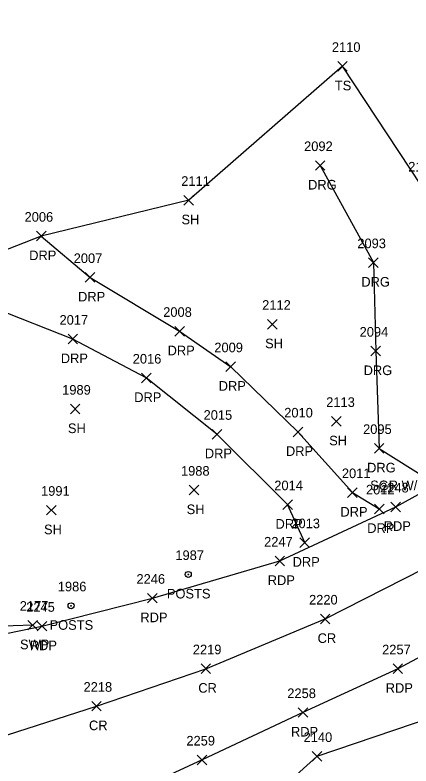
# Model space of a CAD drawing. Extents: x 1616726 to 1619875, y 273782 to 276557.
# Drawn here: x 1616975.5 to 1617057.8, y 276373.3 to 276529.6 of the extents above; entities that cross this region are included whole.
import ezdxf

# ---------------------------------------------------------------- set-up
doc = ezdxf.new("R2010")
doc.units = 0
for name, color, linetype in [('L_A', 7, 'Continuous'), ('L_I', 7, 'Continuous'), ('L_TIC', 7, 'Continuous'), ('LELB', 7, 'Continuous'), ('LPST', 7, 'Continuous'), ('LSOGP', 7, 'Continuous'), ('P_A', 7, 'Continuous'), ('P_I', 7, 'Continuous'), ('P_TIC', 7, 'Continuous'), ('PET', 7, 'Continuous'), ('PRC', 7, 'Continuous'), ('R_A', 7, 'Continuous'), ('R_C', 7, 'Continuous'), ('R_I', 7, 'Continuous'), ('R_TIC', 7, 'Continuous'), ('RDG', 7, 'Continuous'), ('RDP', 7, 'Continuous'), ('RSW', 7, 'Continuous')]:
    doc.layers.add(name, color=color, linetype=linetype)

msp = doc.modelspace()

# ---------------------------------------------------------------- linework, layer by layer
at = {"layer": 'L_TIC'}
for points in [[(1617042.61, 276517.88), (1617044.61, 276519.88)], [(1617044.61, 276517.88), (1617042.61, 276519.88)], [(1617010.63, 276490), (1617012.63, 276492)], [(1617012.63, 276490), (1617010.63, 276492)], [(1617028.02, 276464.21), (1617030.02, 276466.21)], [(1617030.02, 276464.21), (1617028.02, 276466.21)], [(1616987.01, 276446.55), (1616989.01, 276448.55)], [(1616989.01, 276446.55), (1616987.01, 276448.55)], [(1617041.35, 276444), (1617043.35, 276446)], [(1617043.35, 276444), (1617041.35, 276446)], [(1617011.71, 276429.69), (1617013.71, 276431.69)], [(1617013.71, 276429.69), (1617011.71, 276431.69)], [(1616982.05, 276425.51), (1616984.05, 276427.51)], [(1616984.05, 276425.51), (1616982.05, 276427.51)]]:
    msp.add_lwpolyline(points, dxfattribs=at)
at = {"layer": 'LELB'}
msp.add_lwpolyline([(1617083.01, 276455.2), (1617074.16, 276469.8), (1617060.06, 276493.98), (1617043.61, 276518.88)], dxfattribs=at)
at = {"layer": 'LPST'}
for centre, radius in [((1617011.54, 276413.14), 0.625), ((1617011.54, 276413.14), 0.0833), ((1616987.15, 276406.62), 0.625), ((1616987.15, 276406.62), 0.0833)]:
    msp.add_circle(centre, radius, dxfattribs=at)
at = {"layer": 'LSOGP'}
msp.add_lwpolyline([(1617110.11, 276364.12), (1617113.03, 276383.54), (1617109.95, 276385.21), (1617111.11, 276389.12), (1617115.01, 276408.98), (1617109.21, 276417.76), (1617106.51, 276423.63), (1617105.2, 276425.94), (1617105.81, 276428.23), (1617105.93, 276428.7), (1617104.14, 276431), (1617098, 276438.89), (1617095.99, 276441.39), (1617089.73, 276449.19), (1617088.77, 276449.45), (1617085.55, 276449.8), (1617083.01, 276455.2), (1617074.16, 276469.8), (1617060.06, 276493.98), (1617043.61, 276518.88), (1617011.63, 276491), (1616980.96, 276483.54), (1616950.12, 276471.44)], dxfattribs=at)
at = {"layer": 'P_TIC'}
for points in [[(1617053.69, 276426.2), (1617055.69, 276428.2)], [(1617055.69, 276426.2), (1617053.69, 276428.2)], [(1617029.57, 276414.94), (1617031.57, 276416.94)], [(1617031.57, 276414.94), (1617029.57, 276416.94)], [(1617003.08, 276407.2), (1617005.08, 276409.2)], [(1617005.08, 276407.2), (1617003.08, 276409.2)], [(1617039, 276402.88), (1617041, 276404.88)], [(1617041, 276402.88), (1617039, 276404.88)], [(1616980.09, 276401.37), (1616982.09, 276403.37)], [(1616982.09, 276401.37), (1616980.09, 276403.37)], [(1617014.18, 276392.53), (1617016.18, 276394.53)], [(1617016.18, 276392.53), (1617014.18, 276394.53)], [(1617054.11, 276392.51), (1617056.11, 276394.51)], [(1617056.11, 276392.51), (1617054.11, 276394.51)], [(1616991.45, 276384.73), (1616993.45, 276386.73)], [(1616993.45, 276384.73), (1616991.45, 276386.73)], [(1617034.39, 276383.41), (1617036.39, 276385.41)], [(1617036.39, 276383.41), (1617034.39, 276385.41)], [(1617013.4, 276373.54), (1617015.4, 276375.54)], [(1617015.4, 276373.54), (1617013.4, 276375.54)]]:
    msp.add_lwpolyline(points, dxfattribs=at)
at = {"layer": 'PET'}
msp.add_lwpolyline([(1616962.48, 276398.53), (1616981.09, 276402.37), (1617004.08, 276408.2), (1617030.57, 276415.94), (1617054.69, 276427.2), (1617070.17, 276435.74), (1617083.87, 276444.95), (1617089.73, 276449.19), (1617098, 276438.89), (1617105.93, 276428.7), (1617091.93, 276417.88), (1617075.61, 276407.18), (1617070.48, 276401.74), (1617055.11, 276393.51), (1617035.39, 276384.41), (1617014.4, 276374.54), (1616987.83, 276362.23)], dxfattribs=at)
at = {"layer": 'PRC'}
msp.add_lwpolyline([(1616941.59, 276369.44), (1616967.61, 276377.73), (1616992.45, 276385.73), (1617015.18, 276393.53), (1617040, 276403.88), (1617060.6, 276414.36), (1617077.78, 276424.7), (1617090.54, 276433.25), (1617097.77, 276438.74)], dxfattribs=at)
at = {"layer": 'R_TIC'}
for points in [[(1617037.96, 276497.24), (1617039.96, 276499.24)], [(1617039.96, 276497.24), (1617037.96, 276499.24)], [(1616979.96, 276482.54), (1616981.96, 276484.54)], [(1616981.96, 276482.54), (1616979.96, 276484.54)], [(1617049.03, 276477.03), (1617051.03, 276479.03)], [(1617051.03, 276477.03), (1617049.03, 276479.03)], [(1616990.12, 276473.94), (1616992.12, 276475.94)], [(1616992.12, 276473.94), (1616990.12, 276475.94)], [(1617008.74, 276462.74), (1617010.74, 276464.74)], [(1617010.74, 276462.74), (1617008.74, 276464.74)], [(1616986.53, 276461.11), (1616988.53, 276463.11)], [(1616988.53, 276461.11), (1616986.53, 276463.11)], [(1617049.51, 276458.62), (1617051.51, 276460.62)], [(1617051.51, 276458.62), (1617049.51, 276460.62)], [(1617019.37, 276455.37), (1617021.37, 276457.37)], [(1617021.37, 276455.37), (1617019.37, 276457.37)], [(1617001.8, 276453.02), (1617003.8, 276455.02)], [(1617003.8, 276453.02), (1617001.8, 276455.02)], [(1617033.35, 276441.8), (1617035.35, 276443.8)], [(1617035.35, 276441.8), (1617033.35, 276443.8)], [(1617016.5, 276441.32), (1617018.5, 276443.32)], [(1617018.5, 276441.32), (1617016.5, 276443.32)], [(1617050.23, 276438.37), (1617052.23, 276440.37)], [(1617052.23, 276438.37), (1617050.23, 276440.37)], [(1617044.68, 276429.18), (1617046.68, 276431.18)], [(1617046.68, 276429.18), (1617044.68, 276431.18)], [(1617031.19, 276426.66), (1617033.19, 276428.66)], [(1617033.19, 276426.66), (1617031.19, 276428.66)], [(1617050.26, 276425.78), (1617052.26, 276427.78)], [(1617052.26, 276425.78), (1617050.26, 276427.78)], [(1617034.74, 276418.76), (1617036.74, 276420.76)], [(1617036.74, 276418.76), (1617034.74, 276420.76)], [(1616978.18, 276401.58), (1616980.18, 276403.58)], [(1616980.18, 276401.58), (1616978.18, 276403.58)], [(1617037.3, 276374.27), (1617039.3, 276376.27)], [(1617039.3, 276374.27), (1617037.3, 276376.27)]]:
    msp.add_lwpolyline(points, dxfattribs=at)
at = {"layer": 'RDG'}
for points in [[(1617038.96, 276498.24), (1617050.03, 276478.03), (1617050.51, 276459.62), (1617051.23, 276439.37), (1617061.27, 276433.04)], [(1617077.03, 276406.73), (1617072.61, 276398.75), (1617072.54, 276395.54), (1617066.25, 276384.77), (1617038.3, 276375.27), (1617027.72, 276365.78), (1617031.2, 276356.18), (1617047.04, 276352.12), (1617054.6, 276351.72)]]:
    msp.add_lwpolyline(points, dxfattribs=at)
at = {"layer": 'RDP'}
for points in [[(1616980.96, 276483.54), (1616991.12, 276474.94), (1617009.74, 276463.74), (1617020.37, 276456.37), (1617034.35, 276442.8), (1617045.68, 276430.18), (1617051.26, 276426.78)], [(1617035.74, 276419.76), (1617032.19, 276427.66), (1617017.5, 276442.32), (1617002.8, 276454.02), (1616987.53, 276462.11), (1616971.33, 276468.46), (1616960.11, 276471), (1616943.03, 276471.75), (1616932.72, 276469.15), (1616916.98, 276454.45), (1616902.69, 276441.64), (1616898.05, 276435.6)]]:
    msp.add_lwpolyline(points, dxfattribs=at)
at = {"layer": 'RSW'}
msp.add_lwpolyline([(1616979.18, 276402.58), (1616970.93, 276402.28), (1616960.75, 276403.53), (1616947.75, 276406.07), (1616931.67, 276410.77), (1616917.99, 276418.15), (1616909.17, 276424.63), (1616898.61, 276433.98), (1616883.06, 276447.99), (1616873.99, 276456.3), (1616860.19, 276469.07), (1616843.86, 276484.23), (1616830.87, 276497.35), (1616815.83, 276511.33), (1616796.2, 276529.55)], dxfattribs=at)

# ---------------------------------------------------------------- texts
at = {"layer": 'L_A'}
for s, p in [('TS', (1617042.02, 276513.88)), ('SH', (1617010.12, 276486)), ('SH', (1617027.51, 276460.21)), ('SH', (1616986.5, 276442.55)), ('SH', (1617040.84, 276440)), ('SH', (1617011.2, 276425.69)), ('SH', (1616981.53, 276421.51)), ('POSTS', (1617007.09, 276408.14)), ('POSTS', (1616982.69, 276401.62))]:
    msp.add_text(s, height=2, dxfattribs=at).set_placement(p)
at = {"layer": 'L_I'}
for s, p in [('2110', (1617041.4, 276521.88)), ('2109', (1617057.28, 276496.98)), ('2111', (1617010.07, 276494)), ('2112', (1617026.9, 276468.21)), ('1989', (1616985.31, 276450.55)), ('2113', (1617040.22, 276448)), ('1988', (1617010.02, 276433.69)), ('1991', (1616980.92, 276429.51)), ('1987', (1617008.85, 276416.14)), ('1986', (1616984.4, 276409.62))]:
    msp.add_text(s, height=2, dxfattribs=at).set_placement(p)
at = {"layer": 'P_A'}
for s, p in [('RDP', (1617052.18, 276422.2)), ('RDP', (1617028.06, 276410.94)), ('RDP', (1617001.57, 276403.2)), ('CR', (1617038.43, 276398.88)), ('RDP', (1616978.58, 276397.37)), ('CR', (1617013.61, 276388.53)), ('RDP', (1617052.6, 276388.51)), ('CR', (1616990.88, 276380.73)), ('RDP', (1617032.88, 276379.41))]:
    msp.add_text(s, height=2, dxfattribs=at).set_placement(p)
at = {"layer": 'P_I'}
for s, p in [('2248', (1617051.43, 276430.2)), ('2247', (1617027.31, 276418.94)), ('2246', (1617000.76, 276411.2)), ('2220', (1617036.65, 276406.88)), ('2245', (1616977.83, 276405.37)), ('2219', (1617012.48, 276396.53)), ('2257', (1617051.85, 276396.51)), ('2218', (1616989.75, 276388.73)), ('2258', (1617032.13, 276387.41)), ('2259', (1617011.14, 276377.54))]:
    msp.add_text(s, height=2, dxfattribs=at).set_placement(p)
at = {"layer": 'R_A'}
for s, p in [('DRG', (1617036.45, 276493.24)), ('DRP', (1616978.45, 276478.54)), ('DRG', (1617047.52, 276473.03)), ('DRP', (1616988.61, 276469.94)), ('DRP', (1617007.23, 276458.74)), ('DRP', (1616985.02, 276457.11)), ('DRG', (1617048, 276454.62)), ('DRP', (1617017.86, 276451.37)), ('DRP', (1617000.29, 276449.02)), ('DRP', (1617014.98, 276437.32)), ('DRP', (1617031.84, 276437.8)), ('DRG', (1617048.72, 276434.37)), ('DRP', (1617043.17, 276425.18)), ('DRP', (1617029.68, 276422.66)), ('DRP', (1617048.75, 276421.78)), ('DRP', (1617033.23, 276414.76)), ('SWP', (1616976.54, 276397.58))]:
    msp.add_text(s, height=2, dxfattribs=at).set_placement(p)
at = {"layer": 'R_C'}
msp.add_text('SGR W/ WOOD POSTS', height=2, dxfattribs=at).set_placement((1617049.36, 276430.67))
at = {"layer": 'R_I'}
for s, p in [('2092', (1617035.62, 276501.24)), ('2006', (1616977.49, 276486.54)), ('2093', (1617046.69, 276481.03)), ('2007', (1616987.7, 276477.94)), ('2008', (1617006.32, 276466.74)), ('2017', (1616984.76, 276465.11)), ('2094', (1617047.17, 276462.62)), ('2009', (1617016.95, 276459.37)), ('2016', (1616999.98, 276457.02)), ('2015', (1617014.72, 276445.32)), ('2010', (1617031.49, 276445.8)), ('2095', (1617047.89, 276442.37)), ('2011', (1617043.48, 276433.18)), ('2014', (1617029.42, 276430.66)), ('2012', (1617048.49, 276429.78)), ('2013', (1617032.97, 276422.76)), ('2177', (1616976.48, 276405.58)), ('2140', (1617035.52, 276378.27))]:
    msp.add_text(s, height=2, dxfattribs=at).set_placement(p)

doc.saveas('drawing.dxf')
